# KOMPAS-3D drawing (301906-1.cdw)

Views: Вид 1, Вид 2, Вид А, Вид Б, Вид Г, Вид Д, Вид Е, Вид Ж, Вид К, Вид И, Вид В, Вид Л, Вид H, Вид М
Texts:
  Аппарат вертикальный с механическим  перемешивающим устройством
  денис
  Текст на чертеже
  Размерные надписи
  Шероховатость
  Линия-выноска #1
  Линия-выноска #2
  Линия-выноска #3
  Отклонения формы и база
  Заголовок таблицы
  Ячейка таблицы
  Стрелка вида
  Обозначение изменения
  Фигурная скобка
  Номер узла
  Марка координационной оси
  VRCB
  Выносная надпись
  Обозначение узла
  Марка/позиционное обозначение с линией-выноской
  Марка/позиционное обозначение на линии
  Марка/позиционное обозначение без линии-выноски
  Назначение
  Уловный проход, мм
  Условное давление, МПа
  Для загрузки
  Резервный
  Технологический
  Для манометра
  Для термометра
  Вход и выход теплоносителя
  Для слива
  Люк
  Технические требования
  * Размеры для справок.
  Провести гидравлические испытания в течении 10 мин при
  давлении в корпусе 1,441 МПа и при давлении в рубашке 1.441 МПа.
  Давление в корпус и рубашку подавать раздельно.
  Испытания работы перемешивающего устройства проводить не
  менее 30 мин.
  Истинное положение штуцеров на виде А.
  Технические характеристика аппарата.
  2. Давление в аппарате, МПа                                        0,3
  3. Давление в рубашке, МПа                                         0,6
  4. Мощность привода, кВт                                          10
  5. Число оборотов мешалки, об/мин                               170
  6. Среда: водный раствор Pb(NO3)2 , %                           30
  7. Рабочая температура,  С                                         80
  Symbol type A
  js9
  Основной вид
  Корпус
  Мешалка
  Крышка люка
  Уплотнение торцевое
  Привод
  Вал
  Прокладка люка
  Кольцо стопорное
  Болт ГОСТ 15589-70
  Болт
  ГОСТ
  Баранов Д.А
  Аппарат вертикальный
  с механическим
  перемешивающим устройством
  СПбГТИ(ТУ)
  группа 364
Dimensions and other numbers on the sheet: 105.11.00.00.000СБ; 7; 250; 0,3; 100; 200; 150; 80; 0,6; 500; 3138; 3256; 4030; 5299; 5907; 4 отв; 18; 170; 2400; 280; 8 отв; 225; 335; 12 отв; 110; 14; 580; 20 отв; 23; 800; 750; 392,81; 1120; 3353; 3146; 22; 1; 2; 3; 4; 5; 6; 8; 9; 10; 11; 15; 19; 12; 16; 20; 13; 17; 21; 330; 350; 65; 48,53; 2,67; 45; 105.16.01.00.000; 105.16.02.00.000; 105.16.03.00.000; 105.16.04.00.000; 105.16.05.00.000; 105.16.00.00.001; 105.16.00.00.002; 105.16.00.00.003; 1:15; 105.11.00.00.000СБ-; 4846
